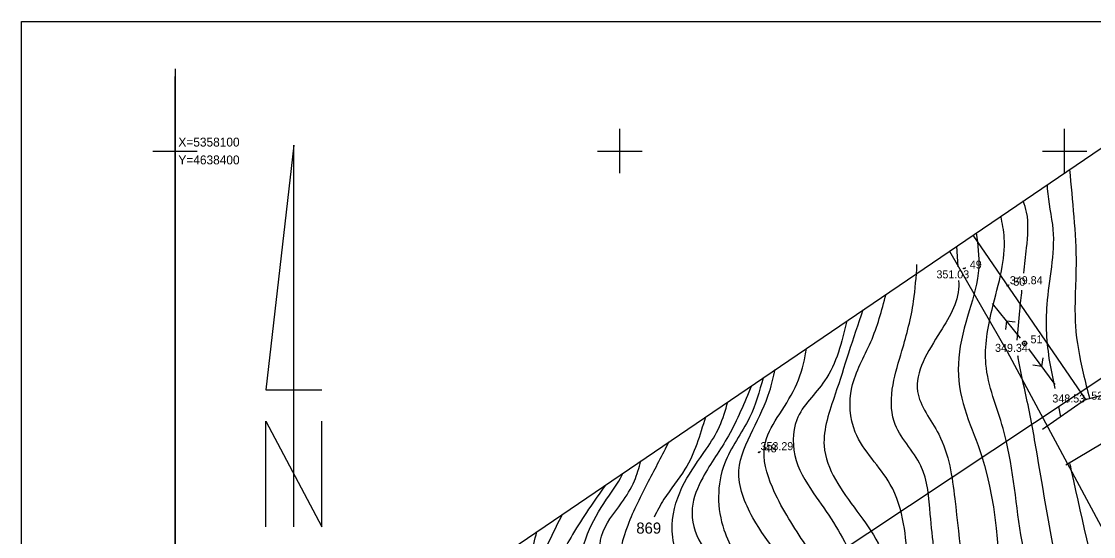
# Model space of a CAD drawing. Extents: x 4632591 to 4651936, y 5351032 to 5369988.
# Drawn here: x 4638382.7 to 4638503.3, y 5358056.7 to 5358114.6 of the extents above; entities that cross this region are included whole.
import ezdxf

# ---------------------------------------------------------------- set-up
doc = ezdxf.new("R2010")
doc.units = 0
for name, color, linetype in [('EBUPP_312', 7, 'Continuous'), ('EDZPD_211', 7, 'Continuous'), ('EDZPD_219', 7, 'Continuous'), ('EUZPU_218', 7, 'Continuous'), ('EUZPU_424', 7, 'Continuous'), ('UEEPA_510', 7, 'Continuous'), ('UEETA_516', 7, 'Continuous'), ('UGGPO_583', 7, 'Continuous'), ('Warstwa 25', 7, 'Continuous'), ('Warstwa 40', 7, 'Continuous'), ('Warstwa 60', 7, 'Continuous'), ('Warstwa 62', 7, 'Continuous'), ('WUKPS_403', 7, 'Continuous'), ('WWRPH_811', 7, 'Continuous'), ('WWRPH_812', 7, 'Continuous'), ('WWRPH_814', 7, 'Continuous')]:
    doc.layers.add(name, color=color, linetype=linetype)

msp = doc.modelspace()

# ---------------------------------------------------------------- linework, layer by layer
at = {"layer": 'EBUPP_312'}
msp.add_lwpolyline([(4638382.73, 5358114.56), (4638591.48, 5358114.56), (4638591.48, 5357941.24), (4638382.73, 5357941.24), (4638382.73, 5358114.56)], dxfattribs=at)
at = {"layer": 'EDZPD_219'}
msp.add_line((4638429.37, 5358024.9), (4638519.22, 5358084.49), dxfattribs=at)
at = {"layer": 'EUZPU_218'}
msp.add_line((4638489.68, 5358090.54), (4638502.33, 5358072.06), dxfattribs=at)
at = {"layer": 'EUZPU_424'}
for p, q in [((4638502.33, 5358072.06), (4638497.51, 5358068.69)), ((4638505.48, 5358067.87), (4638500.14, 5358064.69))]:
    msp.add_line(p, q, dxfattribs=at)
msp.add_lwpolyline([(4638502.33, 5358072.06), (4638516.32, 5358075.71), (4638526.85, 5358076.56)], dxfattribs=at)
at = {"layer": 'UEEPA_510'}
msp.add_circle((4638495.5, 5358078.39), 0.25, dxfattribs=at)
at = {"layer": 'UEETA_516'}
for p, q in [((4638495.03, 5358078.97), (4638491.89, 5358082.87)), ((4638493.46, 5358080.92), (4638493.35, 5358079.93)), ((4638493.46, 5358080.92), (4638494.45, 5358080.81)), ((4638495.94, 5358077.78), (4638498.89, 5358073.75)), ((4638497.42, 5358075.77), (4638496.43, 5358075.92)), ((4638497.42, 5358075.77), (4638497.57, 5358076.75))]:
    msp.add_line(p, q, dxfattribs=at)
at = {"layer": 'UGGPO_583'}
msp.add_lwpolyline([(4638487.07, 5358088.76), (4638493.53, 5358077.47), (4638509.46, 5358047.84), (4638521.2, 5358032.94), (4638525.99, 5358026.32)], dxfattribs=at)
at = {"layer": 'Warstwa 25'}
for points in [[(4638413.33, 5358057.75), (4638413.33, 5358100.67), (4638410.19, 5358073.15), (4638416.48, 5358073.15)], [(4638410.19, 5358057.75), (4638410.19, 5358069.64), (4638416.48, 5358057.75), (4638416.48, 5358069.64)]]:
    msp.add_lwpolyline(points, dxfattribs=at)
at = {"layer": 'Warstwa 40'}
msp.add_line((4638385.83, 5358019.95), (4638506.88, 5358102.23), dxfattribs=at)
at = {"layer": 'Warstwa 60'}
for p, q in [((4638400, 5358109.24), (4638400, 5358000)), ((4638400, 5358000), (4638400, 5358108.37)), ((4638450, 5358097.5), (4638450, 5358102.5)), ((4638500, 5358097.5), (4638500, 5358102.5)), ((4638397.5, 5358100), (4638400, 5358100)), ((4638400, 5358100), (4638402.5, 5358100)), ((4638447.5, 5358100), (4638452.5, 5358100)), ((4638497.5, 5358100), (4638502.5, 5358100))]:
    msp.add_line(p, q, dxfattribs=at)
at = {"layer": 'WUKPS_403'}
for centre in [(4638488.67, 5358086.79), (4638493.57, 5358084.86), (4638495.5, 5358078.39), (4638502.33, 5358072.06), (4638465.62, 5358066.14)]:
    msp.add_circle(centre, 0.045, dxfattribs=at)
at = {"layer": 'WWRPH_811'}
for p, q in [((4638487.85, 5358089.29), (4638487.98, 5358086.99)), ((4638499.58, 5358070.14), (4638499.35, 5358071.28))]:
    msp.add_line(p, q, dxfattribs=at)
for points in [[(4638498.94, 5358073.31), (4638498.34, 5358076.3), (4638498.03, 5358082.74), (4638498.72, 5358091.18), (4638498.09, 5358095.75), (4638498.07, 5358096.24)], [(4638488.07, 5358085.46), (4638488.09, 5358085.18), (4638486.02, 5358079.68), (4638483.46, 5358072.99), (4638485.84, 5358068.17), (4638487.65, 5358060.92), (4638490.21, 5358046.85), (4638491.89, 5358043.01)], [(4638486.78, 5358042.09), (4638482.96, 5358049.73), (4638481.9, 5358058.1), (4638480.4, 5358062.54), (4638476.46, 5358068.42), (4638476.08, 5358073.42), (4638478.21, 5358078.55), (4638479.92, 5358083.9)], [(4638475.51, 5358080.9), (4638473.02, 5358074.17), (4638469.89, 5358069.8), (4638469.83, 5358065.23), (4638472.08, 5358061.11), (4638476.08, 5358054.35), (4638479.65, 5358042.72), (4638480.37, 5358041.41)], [(4638474.59, 5358039.31), (4638472.58, 5358044.1), (4638470.45, 5358050.35), (4638464.95, 5358058.79), (4638463.39, 5358064.11), (4638464.95, 5358068.67), (4638466.83, 5358072.99), (4638467.47, 5358075.44)], [(4638459.61, 5358070.1), (4638457.32, 5358064.23), (4638454.95, 5358060.86), (4638453.85, 5358058.85)], [(4638447.94, 5358049.13), (4638447.82, 5358052.91), (4638447.94, 5358056.73), (4638450.2, 5358060.48), (4638451.63, 5358062.92), (4638452.36, 5358065.17)], [(4638504.75, 5358046.17), (4638504.66, 5358046.6), (4638500.78, 5358064.04), (4638500.58, 5358064.95)], [(4638448.37, 5358062.46), (4638444.69, 5358056.92), (4638442.5, 5358051.79), (4638442.75, 5358047.41), (4638445.76, 5358041.85), (4638448.38, 5358038.78), (4638451.43, 5358034.16)], [(4638445.31, 5358032.23), (4638443.94, 5358034.09), (4638438.63, 5358040.66), (4638437.44, 5358044.97), (4638438.19, 5358050.29), (4638439.94, 5358054.48), (4638440.65, 5358057.21)]]:
    msp.add_spline(points, degree=3, dxfattribs=at)
at = {"layer": 'WWRPH_812'}
for points in [[(4638500.55, 5358097.93), (4638501.03, 5358092.62), (4638501.28, 5358087.18), (4638501.22, 5358080.36), (4638502.09, 5358075.05), (4638502.8, 5358072.18)], [(4638495.42, 5358086.28), (4638495.72, 5358089.12), (4638495.72, 5358093.12), (4638495.35, 5358094.39)], [(4638490.06, 5358090.79), (4638490.34, 5358086.87), (4638489.28, 5358082.05), (4638488.09, 5358076.74), (4638488.59, 5358071.61), (4638490.28, 5358066.92), (4638492.88, 5358047.93)], [(4638507.89, 5358014.06), (4638504.03, 5358018.52), (4638499.47, 5358023.53), (4638496.34, 5358028.84), (4638494.03, 5358033.09), (4638490.65, 5358040.53), (4638486.15, 5358051.16), (4638484.9, 5358059.17), (4638483.84, 5358064.61), (4638480.83, 5358069.61), (4638480.71, 5358073.74), (4638481.71, 5358077.55), (4638483.02, 5358083.12), (4638483.4, 5358087.24)], [(4638494.67, 5358078.73), (4638494.96, 5358082.05), (4638495.2, 5358084.36)], [(4638477.32, 5358082.14), (4638475.71, 5358077.3), (4638474.21, 5358072.67), (4638472.96, 5358066.86), (4638476.64, 5358059.54), (4638479.02, 5358055.92), (4638482.96, 5358042.66), (4638485.77, 5358038.22), (4638488.46, 5358034.53), (4638490.71, 5358029.34), (4638492.96, 5358024.03), (4638495.84, 5358020.96), (4638500.03, 5358016.96), (4638502.78, 5358014.27), (4638504.78, 5358011.96)], [(4638501.56, 5358009.8), (4638497.03, 5358013.71), (4638491.59, 5358019.34), (4638488.71, 5358023.4), (4638486.9, 5358027.53), (4638484.84, 5358031.09), (4638481.08, 5358034.84), (4638478.46, 5358039.1), (4638473.08, 5358052.23), (4638470.64, 5358056.1), (4638467.14, 5358062.23), (4638466.27, 5358066.86), (4638467.7, 5358070.05), (4638469.7, 5358073.42), (4638470.83, 5358076.99), (4638470.97, 5358077.82)], [(4638510.76, 5358026.73), (4638507.35, 5358031.47), (4638504.16, 5358037.91), (4638501.03, 5358046.22), (4638496.9, 5358065.98), (4638495.72, 5358072.24), (4638494.78, 5358076.74), (4638494.74, 5358076.97)], [(4638466.1, 5358074.51), (4638464.58, 5358070.05), (4638461.76, 5358064.86), (4638461.7, 5358057.42), (4638464.58, 5358052.41), (4638469.2, 5358045.97), (4638474.39, 5358034.91), (4638478.4, 5358029.65), (4638483.77, 5358024.46), (4638485.46, 5358021.84), (4638488.27, 5358017.9), (4638491.15, 5358013.96), (4638494.46, 5358009.9), (4638497.43, 5358007.02)], [(4638467.04, 5358035.09), (4638460.76, 5358047.47), (4638457.2, 5358052.6), (4638455.89, 5358057.98), (4638457.26, 5358062.73), (4638459.7, 5358066.48), (4638461.2, 5358069.05), (4638462.14, 5358071.81)], [(4638455.51, 5358067.31), (4638453.2, 5358062.86), (4638450.88, 5358057.92), (4638449.95, 5358053.23), (4638452.7, 5358046.79), (4638456.2, 5358042.6), (4638465.31, 5358026.8)], [(4638484.97, 5357998.63), (4638482.4, 5358003.02), (4638479.77, 5358007.14), (4638472.96, 5358013.02), (4638466.7, 5358017.59), (4638462.89, 5358020.78), (4638458.7, 5358027.34), (4638450.82, 5358039.35), (4638447.07, 5358044.35), (4638445.13, 5358047.29), (4638445.13, 5358052.41), (4638446.38, 5358056.98), (4638448.51, 5358060.86), (4638450.26, 5358063.61), (4638450.35, 5358063.8)], [(4638443.52, 5358059.16), (4638441.07, 5358053.66), (4638440.07, 5358049.1), (4638439.67, 5358045.4)]]:
    msp.add_spline(points, degree=3, dxfattribs=at)
at = {"layer": 'WWRPH_814'}
for points in [[(4638497.94, 5358045.09), (4638495.09, 5358056.85), (4638493.09, 5358068.8), (4638491.15, 5358076.05), (4638491.84, 5358082.18), (4638492.9, 5358086.55), (4638493.21, 5358090.24), (4638492.84, 5358092.69)], [(4638464.78, 5358073.62), (4638462.2, 5358067.98), (4638459.32, 5358063.29), (4638458.14, 5358059.86), (4638459.14, 5358055.85), (4638462.58, 5358051.91), (4638466.39, 5358043.85), (4638468.78, 5358039.05)]]:
    msp.add_spline(points, degree=3, dxfattribs=at)

# ---------------------------------------------------------------- texts
at = {"layer": 'EDZPD_211'}
msp.add_text('869', height=1.25, dxfattribs=at).set_placement((4638451.85, 5358057))
at = {"layer": 'Warstwa 25'}
for s, p in [(' X=5358100 ', (4638400, 5358100.5)), (' Y=4638400 ', (4638400, 5358098.5))]:
    msp.add_text(s, height=1, dxfattribs=at).set_placement(p)
at = {"layer": 'Warstwa 62'}
for s, p in [('. 49', (4638488.67, 5358086.79)), ('. 50', (4638493.57, 5358084.86)), ('. 51', (4638495.5, 5358078.39)), ('. 52', (4638502.33, 5358072.06)), ('. 48', (4638465.62, 5358066.14))]:
    msp.add_text(s, height=0.9, dxfattribs=at).set_placement(p)
at = {"layer": 'WUKPS_403'}
for s, p in [('351.03', (4638485.59, 5358085.69)), ('349.84', (4638493.84, 5358085.03)), ('349.34', (4638492.18, 5358077.43)), ('348.53', (4638498.62, 5358071.74)), ('353.29', (4638465.81, 5358066.38))]:
    msp.add_text(s, height=0.9, dxfattribs=at).set_placement(p)

doc.saveas('drawing.dxf')
